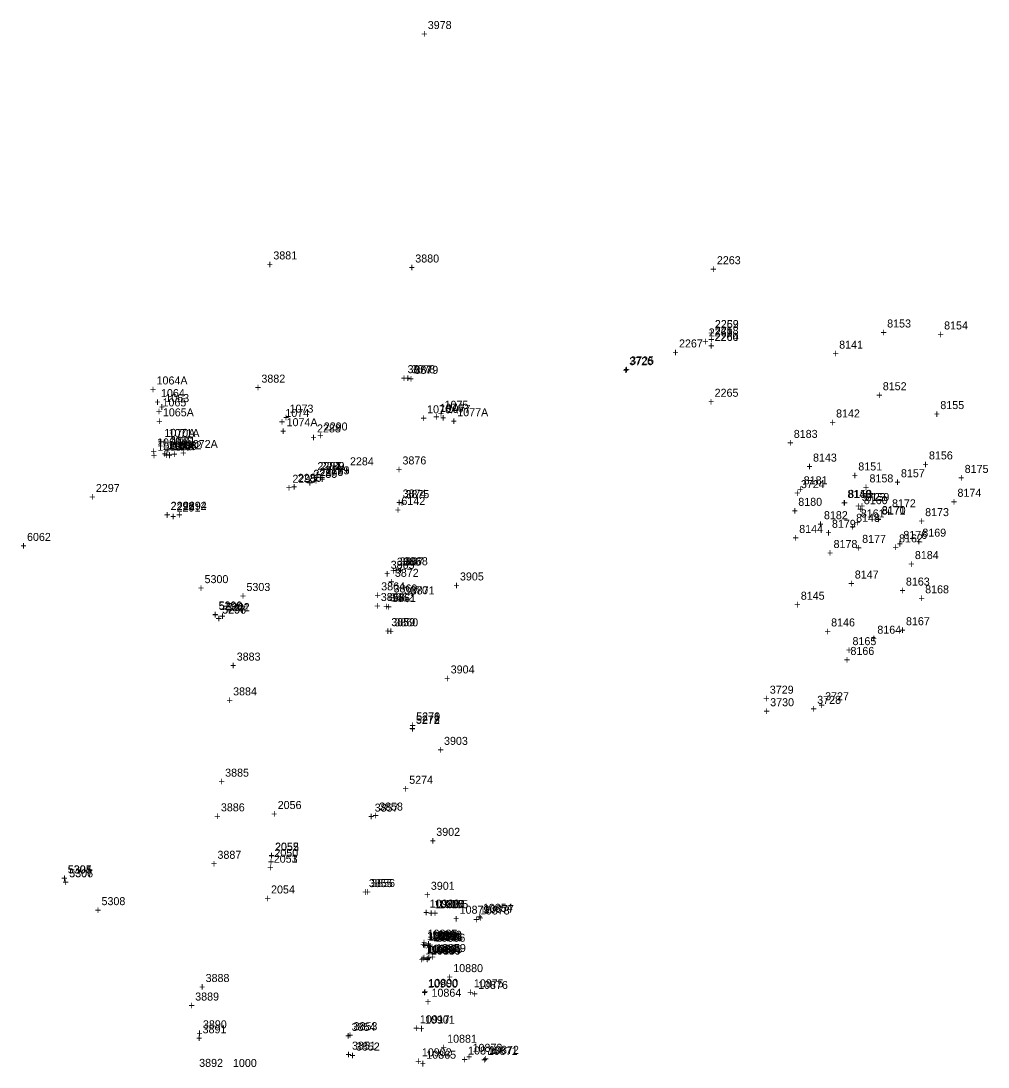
# Model space of a CAD drawing. Extents: x 1136220 to 1137808, y 528804 to 531215.
# Drawn here: x 1137338.4 to 1137640.4, y 530222.6 to 530549.3 of the extents above; entities that cross this region are included whole.
import ezdxf

# ---------------------------------------------------------------- set-up
doc = ezdxf.new("R2010")
doc.units = 0
for name, color, linetype in [('S_Buildings_SillElevation', 7, 'Continuous'), ('S_Curb_Type_1', 7, 'Continuous'), ('S_Drainage_CB', 7, 'Continuous'), ('S_Drainage_Culvert_Top', 7, 'Continuous'), ('S_Drainage_Invert', 7, 'Continuous'), ('S_Drainage_Sump', 7, 'Continuous'), ('S_Fencing_Gate', 7, 'Continuous'), ('S_Fencing_Picket', 7, 'Continuous'), ('S_Fencing_PostAndRail', 7, 'Continuous'), ('S_Ground_Elevation', 7, 'Continuous'), ('S_Ground_SpotElevation', 7, 'Continuous'), ('S_Misc_MiscItems', 7, 'Continuous'), ('S_Property_ConcPad', 7, 'Continuous'), ('S_Roadway_Sidewalks', 7, 'Continuous'), ('S_Trees_Decid_NonPay', 7, 'Continuous'), ('S_Trees_Decid_Pay', 7, 'Continuous'), ('S_Utilities_GuyWire3', 7, 'Continuous'), ('S_Utilities_Pole_Power', 7, 'Continuous'), ('S_Utilities_UG_Sanitary_MH', 7, 'Continuous'), ('S_Utilities_UG_Water_Gate', 7, 'Continuous'), ('S_Utilities_UG_Water_Line', 7, 'Continuous')]:
    doc.layers.add(name, color=color, linetype=linetype)

msp = doc.modelspace()

# ---------------------------------------------------------------- texts
at = {"layer": 'S_Buildings_SillElevation'}
for s, p in [('3881', (1137417.23, 530474.85)), ('+', (1137415.17, 530472.1)), ('3882', (1137413.5, 530436.37)), ('+', (1137411.44, 530433.62)), ('3905', (1137475.51, 530374.59)), ('+', (1137473.45, 530371.84)), ('3883', (1137405.79, 530349.56)), ('+', (1137403.72, 530346.81)), ('3904', (1137472.62, 530345.55)), ('+', (1137470.56, 530342.8)), ('3884', (1137404.66, 530338.7)), ('+', (1137402.6, 530335.95)), ('3903', (1137470.54, 530323.24)), ('+', (1137468.48, 530320.49)), ('3885', (1137402.18, 530313.31)), ('+', (1137400.12, 530310.56)), ('3886', (1137400.85, 530302.48)), ('+', (1137398.79, 530299.73)), ('3902', (1137468.11, 530294.83)), ('+', (1137466.05, 530292.08)), ('3887', (1137399.78, 530287.66)), ('+', (1137397.72, 530284.91)), ('3901', (1137466.42, 530277.98)), ('+', (1137464.36, 530275.23)), ('3888', (1137396.08, 530249.19)), ('3889', (1137392.83, 530243.39)), ('+', (1137394.02, 530246.44)), ('+', (1137390.77, 530240.64)), ('3890', (1137395.24, 530234.72)), ('+', (1137393.18, 530231.97)), ('3892', (1137394.07, 530222.68))]:
    msp.add_text(s, height=2.5, dxfattribs=at).set_placement(p)
at = {"layer": 'S_Curb_Type_1'}
for s, p in [('10892', (1137465.31, 530262.36)), ('10891', (1137466.7, 530262.22)), ('+', (1137463.25, 530259.61)), ('+', (1137464.63, 530259.47)), ('10893', (1137465.04, 530258.1)), ('10894', (1137466.43, 530257.96)), ('+', (1137462.98, 530255.35)), ('+', (1137464.37, 530255.21))]:
    msp.add_text(s, height=2.5, dxfattribs=at).set_placement(p)
at = {"layer": 'S_Drainage_CB'}
for s, p in [('3725', (1137528.67, 530442.05)), ('+', (1137526.6, 530439.3)), ('1066', (1137385.83, 530415.34)), ('+', (1137383.77, 530412.59)), ('5296', (1137401.28, 530364.21)), ('+', (1137399.22, 530361.46)), ('5270', (1137461.86, 530330.9)), ('+', (1137459.8, 530328.15)), ('5304', (1137353.01, 530283.13)), ('+', (1137350.95, 530280.38)), ('1000', (1137404.62, 530222.65))]:
    msp.add_text(s, height=2.5, dxfattribs=at).set_placement(p)
at = {"layer": 'S_Drainage_Culvert_Top'}
for s, p in [('2263', (1137555.75, 530473.35)), ('+', (1137553.69, 530470.6)), ('2262', (1137555.12, 530453.4)), ('+', (1137553.06, 530450.65)), ('2266', (1137553.21, 530450.8)), ('2264', (1137555.09, 530449.38)), ('2267', (1137543.92, 530447.36)), ('+', (1137551.15, 530448.05)), ('+', (1137553.02, 530446.63)), ('+', (1137541.85, 530444.61)), ('1064A', (1137380.76, 530435.8)), ('+', (1137378.7, 530433.05)), ('2265', (1137555.04, 530431.96)), ('1076A', (1137465.25, 530426.79)), ('+', (1137552.97, 530429.21)), ('1065A', (1137382.73, 530425.84)), ('1074A', (1137421.37, 530422.77)), ('+', (1137463.19, 530424.04)), ('+', (1137472.61, 530423.11)), ('1077A', (1137474.67, 530425.86)), ('+', (1137380.67, 530423.09)), ('1070A', (1137383.21, 530419.44)), ('+', (1137419.31, 530420.02)), ('2288', (1137430.87, 530420.82)), ('2290', (1137432.97, 530421.43)), ('1069A', (1137380.92, 530416.46)), ('+', (1137381.15, 530416.69)), ('+', (1137382.44, 530416.62)), ('1071A', (1137384.5, 530419.37)), ('+', (1137428.81, 530418.07)), ('+', (1137430.91, 530418.68)), ('+', (1137378.86, 530413.71)), ('1068A', (1137381.02, 530415.11)), ('1072A', (1137390.2, 530415.96)), ('+', (1137378.96, 530412.36)), ('+', (1137388.14, 530413.21)), ('2284', (1137441.16, 530410.54)), ('2285', (1137429.75, 530406.63)), ('2287', (1137431.01, 530409.04)), ('2289', (1137432.02, 530409.07)), ('2283', (1137433.57, 530407.73)), ('+', (1137439.1, 530407.79)), ('2295', (1137423.19, 530405.1)), ('2286', (1137424.84, 530405.38)), ('+', (1137427.69, 530403.88)), ('+', (1137428.95, 530406.29)), ('+', (1137429.96, 530406.32)), ('+', (1137431.51, 530404.98)), ('3724', (1137581.98, 530403.42)), ('2297', (1137361.81, 530402.21)), ('+', (1137421.13, 530402.35)), ('+', (1137422.77, 530402.63)), ('+', (1137579.91, 530400.67)), ('+', (1137359.75, 530399.46)), ('2296', (1137385.18, 530396.67)), ('2294', (1137389, 530396.67)), ('+', (1137383.12, 530393.92)), ('+', (1137386.93, 530393.92)), ('6062', (1137340.3, 530386.93)), ('+', (1137338.24, 530384.18)), ('5300', (1137395.75, 530373.75)), ('+', (1137393.68, 530371)), ('5303', (1137408.83, 530371.3)), ('+', (1137406.77, 530368.55)), ('5299', (1137400.14, 530365.52)), ('5302', (1137402.38, 530365)), ('+', (1137398.08, 530362.77)), ('+', (1137400.32, 530362.25)), ('3729', (1137572.28, 530339.23)), ('+', (1137570.22, 530336.48)), ('3730', (1137572.4, 530335.31)), ('+', (1137570.34, 530332.56)), ('5273', (1137461.75, 530329.91)), ('+', (1137459.69, 530327.16)), ('5274', (1137459.67, 530311.08)), ('+', (1137457.61, 530308.33)), ('2056', (1137418.59, 530303.21)), ('+', (1137416.53, 530300.46)), ('2055', (1137417.77, 530290.15)), ('+', (1137415.7, 530287.4)), ('2053', (1137417.36, 530286.44)), ('+', (1137415.3, 530283.69)), ('5307', (1137353.46, 530281.92)), ('+', (1137351.4, 530279.17)), ('2054', (1137416.52, 530276.84)), ('5308', (1137363.57, 530273.18)), ('+', (1137414.46, 530274.09)), ('+', (1137361.51, 530270.43))]:
    msp.add_text(s, height=2.5, dxfattribs=at).set_placement(p)
at = {"layer": 'S_Drainage_Invert'}
for s, p in [('2259', (1137555.12, 530453.43)), ('+', (1137553.06, 530450.68)), ('2261', (1137553.19, 530450.79)), ('2260', (1137555.04, 530449.43)), ('+', (1137551.13, 530448.04)), ('+', (1137552.98, 530446.68)), ('1064', (1137382.14, 530431.85)), ('+', (1137380.08, 530429.1)), ('1065', (1137382.61, 530428.94)), ('1076', (1137469.21, 530427.25)), ('1077', (1137471.34, 530426.92)), ('+', (1137380.55, 530426.19)), ('1074', (1137420.99, 530425.65)), ('+', (1137467.15, 530424.5)), ('+', (1137469.28, 530424.17)), ('+', (1137418.93, 530422.9)), ('1070', (1137384.8, 530416.95)), ('1071', (1137385.38, 530416.94)), ('+', (1137382.74, 530414.2)), ('+', (1137383.32, 530414.19)), ('1069', (1137384.41, 530415.66)), ('1068', (1137384.87, 530415.28)), ('1072', (1137387.38, 530415.56)), ('+', (1137382.35, 530412.91)), ('+', (1137382.81, 530412.53)), ('+', (1137385.32, 530412.81)), ('2280', (1137429.72, 530406.65)), ('2281', (1137430.99, 530409.04)), ('2282', (1137432.01, 530409.08)), ('2279', (1137433.55, 530407.74)), ('+', (1137427.66, 530403.9)), ('+', (1137428.93, 530406.29)), ('+', (1137429.94, 530406.33)), ('+', (1137431.49, 530404.99)), ('2293', (1137385.12, 530396.57)), ('2292', (1137388.94, 530396.63)), ('3723', (1137601.01, 530399.36)), ('+', (1137383.06, 530393.82)), ('+', (1137386.88, 530393.88)), ('+', (1137598.95, 530396.61)), ('5298', (1137400.2, 530365.4)), ('5301', (1137402.44, 530364.94)), ('+', (1137398.14, 530362.65)), ('+', (1137400.38, 530362.19)), ('3728', (1137587.08, 530336.05)), ('3727', (1137589.55, 530337.18)), ('+', (1137585.01, 530333.3)), ('+', (1137587.49, 530334.43)), ('5272', (1137461.77, 530329.8)), ('+', (1137459.71, 530327.05)), ('2052', (1137417.74, 530290.23)), ('+', (1137415.68, 530287.48)), ('2051', (1137417.36, 530286.44)), ('+', (1137415.3, 530283.69)), ('5306', (1137353.49, 530281.87)), ('+', (1137351.43, 530279.12)), ('3891', (1137395.14, 530233.17)), ('+', (1137393.08, 530230.42))]:
    msp.add_text(s, height=2.5, dxfattribs=at).set_placement(p)
at = {"layer": 'S_Drainage_Sump'}
for s, p in [('3726', (1137528.39, 530441.82)), ('+', (1137526.33, 530439.07)), ('1063', (1137383.5, 530430.3)), ('+', (1137381.44, 530427.55)), ('1073', (1137422.3, 530427)), ('1075', (1137470.7, 530428.2)), ('+', (1137420.24, 530424.25)), ('+', (1137468.64, 530425.45)), ('1067', (1137385.9, 530415.2)), ('+', (1137383.84, 530412.45)), ('5297', (1137401.23, 530364.26)), ('+', (1137399.17, 530361.51)), ('5271', (1137461.82, 530330.83)), ('+', (1137459.76, 530328.08)), ('5305', (1137353.1, 530283.08)), ('+', (1137351.04, 530280.33))]:
    msp.add_text(s, height=2.5, dxfattribs=at).set_placement(p)
at = {"layer": 'S_Fencing_Gate'}
for s, p in [('10889', (1137466.42, 530257.71)), ('+', (1137464.36, 530254.96))]:
    msp.add_text(s, height=2.5, dxfattribs=at).set_placement(p)
at = {"layer": 'S_Fencing_Picket'}
for s, p in [('10884', (1137467.66, 530272.24)), ('+', (1137465.59, 530269.49)), ('10888', (1137466.77, 530262.64)), ('+', (1137464.71, 530259.89)), ('10890', (1137465.66, 530247.66)), ('+', (1137463.6, 530244.91))]:
    msp.add_text(s, height=2.5, dxfattribs=at).set_placement(p)
at = {"layer": 'S_Fencing_PostAndRail'}
for s, p in [('10877', (1137483.03, 530270.73)), ('+', (1137480.97, 530267.98)), ('10876', (1137481.17, 530247.01)), ('+', (1137479.1, 530244.26)), ('10873', (1137479.45, 530227.38)), ('10872', (1137484.61, 530226.74)), ('+', (1137477.39, 530224.63)), ('+', (1137482.55, 530223.99))]:
    msp.add_text(s, height=2.5, dxfattribs=at).set_placement(p)
at = {"layer": 'S_Ground_Elevation'}
for s, p in [('8153', (1137608.93, 530453.59)), ('8154', (1137626.71, 530452.98)), ('+', (1137606.87, 530450.84)), ('+', (1137624.65, 530450.23)), ('8141', (1137593.94, 530446.98)), ('+', (1137591.87, 530444.23)), ('8152', (1137607.56, 530434)), ('+', (1137605.5, 530431.25)), ('8155', (1137625.53, 530428.11)), ('8142', (1137592.97, 530425.49)), ('+', (1137623.47, 530425.36)), ('+', (1137590.91, 530422.74)), ('8143', (1137585.77, 530411.71)), ('8156', (1137621.98, 530412.39)), ('+', (1137583.71, 530408.96)), ('8151', (1137599.91, 530408.94)), ('8157', (1137613.23, 530406.82)), ('+', (1137619.92, 530409.64)), ('8175', (1137633.14, 530408.17)), ('+', (1137597.85, 530406.19)), ('8158', (1137603.41, 530405.21)), ('+', (1137611.17, 530404.07)), ('+', (1137631.08, 530405.42)), ('8149', (1137596.53, 530400.34)), ('8150', (1137596.74, 530400.38)), ('+', (1137601.34, 530402.46)), ('8174', (1137630.88, 530400.71)), ('+', (1137594.47, 530397.59)), ('+', (1137594.68, 530397.63)), ('8160', (1137601.64, 530398.41)), ('8159', (1137602.15, 530399.4)), ('8172', (1137610.44, 530397.43)), ('+', (1137628.82, 530397.96)), ('+', (1137599.58, 530395.66)), ('+', (1137600.08, 530396.65)), ('8161', (1137600.7, 530394.26)), ('8171', (1137607.25, 530395.17)), ('8170', (1137607.25, 530395.32)), ('+', (1137608.38, 530394.68)), ('8173', (1137620.79, 530394.68)), ('+', (1137598.64, 530391.51)), ('8148', (1137599.23, 530392.9)), ('+', (1137605.19, 530392.42)), ('+', (1137605.19, 530392.57)), ('+', (1137618.73, 530391.93)), ('8144', (1137581.46, 530389.43)), ('+', (1137597.17, 530390.15)), ('8169', (1137619.91, 530388.26)), ('+', (1137579.4, 530386.68)), ('8162', (1137612.64, 530386.48)), ('+', (1137617.85, 530385.51)), ('+', (1137610.58, 530383.73)), ('8147', (1137598.82, 530375.19)), ('+', (1137596.76, 530372.44)), ('8163', (1137614.78, 530372.99)), ('8168', (1137620.79, 530370.57)), ('8145', (1137581.96, 530368.57)), ('+', (1137612.72, 530370.24)), ('+', (1137618.72, 530367.82)), ('+', (1137579.9, 530365.82)), ('8167', (1137614.8, 530360.61)), ('8146', (1137591.43, 530360.23)), ('8164', (1137605.86, 530357.96)), ('+', (1137612.73, 530357.86)), ('+', (1137589.37, 530357.48)), ('8165', (1137598.1, 530354.39)), ('+', (1137603.8, 530355.21)), ('+', (1137596.04, 530351.64)), ('8166', (1137597.46, 530351.33)), ('+', (1137595.4, 530348.58)), ('10885', (1137467.52, 530272.26)), ('+', (1137465.46, 530269.51)), ('10887', (1137465.4, 530263.03)), ('10886', (1137466.72, 530262.68)), ('+', (1137463.34, 530260.28)), ('+', (1137464.66, 530259.93)), ('10899', (1137466.32, 530257.83)), ('+', (1137464.26, 530255.08)), ('10900', (1137465.51, 530247.41)), ('+', (1137463.45, 530244.66)), ('10901', (1137464.57, 530236.15)), ('+', (1137462.51, 530233.4)), ('10902', (1137463.6, 530225.97)), ('+', (1137461.54, 530223.22))]:
    msp.add_text(s, height=2.5, dxfattribs=at).set_placement(p)
at = {"layer": 'S_Ground_SpotElevation'}
for s, p in [('10879', (1137475.42, 530270.5)), ('+', (1137473.36, 530267.75)), ('10880', (1137473.41, 530252.27)), ('+', (1137471.35, 530249.52)), ('10881', (1137471.51, 530230.22)), ('+', (1137469.45, 530227.47))]:
    msp.add_text(s, height=2.5, dxfattribs=at).set_placement(p)
at = {"layer": 'S_Misc_MiscItems'}
for s, p in [('8184', (1137617.58, 530381.26)), ('+', (1137615.52, 530378.51))]:
    msp.add_text(s, height=2.5, dxfattribs=at).set_placement(p)
at = {"layer": 'S_Property_ConcPad'}
for s, p in [('10855', (1137468.8, 530272.24)), ('10878', (1137481.72, 530270.27)), ('10854', (1137482.67, 530271.1)), ('+', (1137466.74, 530269.49)), ('+', (1137479.65, 530267.52)), ('+', (1137480.61, 530268.35)), ('10896', (1137465.65, 530262.12)), ('10895', (1137467.14, 530261.93)), ('10856', (1137467.89, 530261.75)), ('+', (1137463.59, 530259.37)), ('+', (1137465.07, 530259.18)), ('10897', (1137465.34, 530258.33)), ('+', (1137465.83, 530259)), ('10898', (1137466.89, 530258.26)), ('10859', (1137468.05, 530258.55)), ('+', (1137463.28, 530255.58)), ('+', (1137464.83, 530255.51)), ('+', (1137465.99, 530255.8)), ('10875', (1137479.84, 530247.52)), ('10864', (1137466.62, 530244.58)), ('+', (1137477.78, 530244.77)), ('+', (1137464.56, 530241.83)), ('10865', (1137465.01, 530225.22)), ('10874', (1137478.06, 530226.54)), ('10871', (1137484.22, 530226.41)), ('+', (1137462.95, 530222.47)), ('+', (1137476, 530223.79)), ('+', (1137482.16, 530223.66))]:
    msp.add_text(s, height=2.5, dxfattribs=at).set_placement(p)
at = {"layer": 'S_Roadway_Sidewalks'}
for s, p in [('10920', (1137466.05, 530272.42)), ('+', (1137463.99, 530269.67)), ('10919', (1137465.18, 530262.36)), ('+', (1137463.12, 530259.61)), ('10918', (1137464.67, 530257.8)), ('+', (1137462.61, 530255.05)), ('10917', (1137462.98, 530236.3)), ('+', (1137460.92, 530233.55))]:
    msp.add_text(s, height=2.5, dxfattribs=at).set_placement(p)
at = {"layer": 'S_Trees_Decid_NonPay'}
for s, p in [('8183', (1137579.76, 530419.11)), ('+', (1137577.7, 530416.36))]:
    msp.add_text(s, height=2.5, dxfattribs=at).set_placement(p)
at = {"layer": 'S_Trees_Decid_Pay'}
for s, p in [('8179', (1137591.68, 530391.03)), ('+', (1137589.62, 530388.28)), ('8176', (1137613.98, 530387.57)), ('8178', (1137592.19, 530384.71)), ('8177', (1137601.12, 530386.33)), ('+', (1137611.92, 530384.82)), ('+', (1137590.13, 530381.96)), ('+', (1137599.06, 530383.58))]:
    msp.add_text(s, height=2.5, dxfattribs=at).set_placement(p)
at = {"layer": 'S_Utilities_GuyWire3'}
for s, p in [('8181', (1137582.86, 530404.61)), ('+', (1137580.8, 530401.86)), ('8182', (1137589.18, 530393.72)), ('+', (1137587.12, 530390.97))]:
    msp.add_text(s, height=2.5, dxfattribs=at).set_placement(p)
at = {"layer": 'S_Utilities_Pole_Power'}
for s, p in [('8180', (1137581.17, 530397.89)), ('+', (1137579.11, 530395.14))]:
    msp.add_text(s, height=2.5, dxfattribs=at).set_placement(p)
at = {"layer": 'S_Utilities_UG_Sanitary_MH'}
for s, p in [('2258', (1137555.09, 530451.39)), ('+', (1137553.03, 530448.64)), ('2278', (1137431.65, 530407.25)), ('+', (1137429.58, 530404.5)), ('2291', (1137387.03, 530396.1)), ('+', (1137384.97, 530393.35)), ('2050', (1137417.56, 530288.23)), ('+', (1137415.5, 530285.48))]:
    msp.add_text(s, height=2.5, dxfattribs=at).set_placement(p)
at = {"layer": 'S_Utilities_UG_Water_Gate'}
for s, p in [('3878', (1137460.32, 530439.31)), ('+', (1137458.26, 530436.56)), ('3876', (1137457.56, 530410.82)), ('+', (1137455.5, 530408.07)), ('6142', (1137457.22, 530398.16)), ('+', (1137455.15, 530395.41)), ('3867', (1137456.67, 530379.29)), ('+', (1137454.61, 530376.54)), ('3872', (1137455.18, 530375.72)), ('+', (1137453.12, 530372.97)), ('3862', (1137453.62, 530368.04)), ('3870', (1137458.09, 530370.3)), ('+', (1137451.55, 530365.29)), ('+', (1137456.03, 530367.55))]:
    msp.add_text(s, height=2.5, dxfattribs=at).set_placement(p)
at = {"layer": 'S_Utilities_UG_Water_Line'}
for s, p in [('+', (1137463.4, 530544.05)), ('3978', (1137465.46, 530546.8)), ('3880', (1137461.56, 530473.89)), ('+', (1137459.5, 530471.14)), ('3877', (1137459.15, 530439.32)), ('3879', (1137461.28, 530439.12)), ('+', (1137457.09, 530436.57)), ('+', (1137459.21, 530436.37)), ('3874', (1137457.62, 530400.49)), ('3875', (1137458.49, 530400.3)), ('+', (1137455.56, 530397.74)), ('+', (1137456.43, 530397.55)), ('3865', (1137453.87, 530378.23)), ('3866', (1137455.8, 530379.19)), ('3868', (1137458.03, 530379.35)), ('+', (1137451.81, 530375.48)), ('+', (1137453.74, 530376.44)), ('+', (1137455.97, 530376.6)), ('3864', (1137450.91, 530371.49)), ('3869', (1137454.78, 530370.84)), ('+', (1137448.85, 530368.74)), ('3863', (1137450.78, 530368.17)), ('+', (1137452.72, 530368.09)), ('3861', (1137454.3, 530367.87)), ('3871', (1137460.14, 530370.22)), ('+', (1137448.72, 530365.42)), ('+', (1137452.24, 530365.12)), ('+', (1137458.08, 530367.47)), ('3859', (1137454.08, 530360.32)), ('3860', (1137455.02, 530360.25)), ('+', (1137452.02, 530357.57)), ('+', (1137452.96, 530357.5)), ('3857', (1137448.87, 530302.4)), ('3858', (1137450.26, 530302.73)), ('+', (1137446.81, 530299.65)), ('+', (1137448.19, 530299.98)), ('+', (1137445.73, 530276.09)), ('3855', (1137447.06, 530278.82)), ('3856', (1137447.79, 530278.84)), ('+', (1137445, 530276.08)), ('3854', (1137441.7, 530233.92)), ('3853', (1137442.28, 530234.13)), ('+', (1137439.63, 530231.17)), ('+', (1137440.22, 530231.38)), ('3851', (1137441.78, 530228.06)), ('3852', (1137443.03, 530227.78)), ('+', (1137439.72, 530225.31)), ('+', (1137440.97, 530225.03))]:
    msp.add_text(s, height=2.5, dxfattribs=at).set_placement(p)

doc.saveas('drawing.dxf')
